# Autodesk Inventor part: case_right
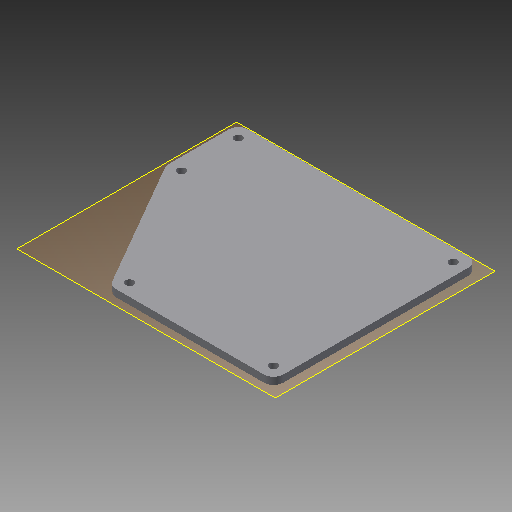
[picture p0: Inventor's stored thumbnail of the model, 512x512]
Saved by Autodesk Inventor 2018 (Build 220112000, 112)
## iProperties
Created: 2017-09
Part Number: case_right
Material: Generic
Document SubType Name: Modeling
Designer: jonas
Density: 1 g/cm^3
Appearance: Default
Mass: 23.7127 g
Surface Area: 170.193 cm^2
Volume: 23.7127 cm^3
Author: jonas
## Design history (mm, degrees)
workplane "Work Plane1"
sketch "Sketch1"
  geometry: L1 (30.736, 8.194)-(5.499, 51.895) reference; L2 (5.499, 51.895)-(10.609, 54.845) reference; L3 (6.775, 61.483)-(10.609, 54.845) reference; L4 (5.998, 61.034)-(6.775, 61.483) reference; L5 (2.998, 62.766)-(2.997, 75.995) reference; L6 (8.996, 81.996)-(90.996, 82.004) reference; L7 (96.997, 76.004)-(97.004, 9.004) reference; L8 (91.004, 3.004)-(39.736, 2.999) reference; L9 (100.004, 3.004)-(99.996, 82.004) reference; L10 (2.996, 84.995)-(96.996, 85.004) reference; L11 (-0.001, 56.224)-(-0.004, 81.995) reference; L12 (31.138, 1.498)-(0.401, 54.724) reference; L13 (97.004, 0.004)-(33.736, -0.002) reference; L14 (100.996, 82.005)-(101.004, 3.005); L15 (97.005, -0.996)-(33.737, -1.002); L16 (30.272, 0.998)-(-0.465, 54.224); L17 (-1.001, 56.224)-(-1.004, 81.995); L18 (2.996, 85.995)-(96.996, 86.004); C1 r 1.45 at (4.249, 56.56) reference; C2 r 1.45 at (4.247, 80.745) reference; C3 r 1.45 at (34.458, 4.248) reference; C4 r 1.45 at (95.754, 4.254) reference; C5 r 1.45 at (95.747, 80.754) reference; A1 r 2 centre (4.998, 62.766) between (2.998, 62.766) and (5.998, 61.034) reference; A2 r 6 centre (2.996, 81.995) between (2.997, 75.995) and (8.996, 81.996) reference; A3 r 6 centre (96.996, 82.004) between (90.996, 82.004) and (96.997, 76.004) reference; A4 r 6 centre (97.004, 3.004) between (97.004, 9.004) and (91.004, 3.004) reference; A5 r 6 centre (33.736, 2.998) between (39.736, 2.999) and (30.736, 8.194) reference; A6 r 3 centre (97.004, 3.004) between (97.004, 0.004) and (100.004, 3.004) reference; A7 r 3 centre (96.996, 82.004) between (99.996, 82.004) and (96.996, 85.004) reference; A8 r 3 centre (2.996, 81.995) between (2.996, 84.995) and (-0.004, 81.995) reference; A9 r 3 centre (2.999, 56.224) between (-0.001, 56.224) and (0.401, 54.724) reference; A10 r 3 centre (33.736, 2.998) between (31.138, 1.498) and (33.736, -0.002) reference; A11 r 4 centre (96.996, 82.004) between (100.996, 82.005) and (96.996, 86.004); A12 r 4 centre (97.004, 3.004) between (97.005, -0.996) and (101.004, 3.005); A13 r 4 centre (33.736, 2.998) between (30.272, 0.998) and (33.737, -1.002); A14 r 4 centre (2.999, 56.224) between (-1.001, 56.224) and (-0.465, 54.224); A15 r 4 centre (2.996, 81.995) between (2.996, 85.995) and (-1.004, 81.995); 1 further point
  constraints: 10 end point, 10 point on circle, 5 centre point, 9 other
  dimensions: "d0" = 1 distance between parallel lines of L18 L10; "d10" = 94 distance of L18.start L18.end (derived); "d11" = 25.77053 distance of L17.start L17.end (derived); "d12" = 61.4641 distance of L16.start L16.end (derived); "d13" = 63.26795 distance of L15.start L15.end (derived); "d14" = 79 distance of L14.start L14.end (derived); "d15" = 1.99966 vertical distance of L16.start L15.end (derived); "d16" = 3.4643 horizontal distance of L15.end L16.start (derived); "d17" = 1.99995 vertical distance of L17.start L16.end (derived); "d18" = 0.53609 horizontal distance of L17.start L16.end (derived); "d19" = 1.76777 distance of A4.centre C4.centre (derived); "d20" = 5.24988 vertical distance of C4.centre L15.start (derived); "d21" = 5.25012 horizontal distance of C4.centre L14.end (derived); "d22" = 5.25007 vertical distance of C3.centre L15.end (derived); "d23" = 4.18547 horizontal distance of C3.centre L16.start (derived); "d24" = 0.72157 horizontal distance of A10.centre C3.centre (derived); "d25" = 5.25 distance from line of C2.centre L17 (derived); "d26" = 5.25 distance from line of C2.centre L18 (derived); "d27" = 5.24997 horizontal distance of C1.centre L17.start (derived); "d28" = 0.33545 vertical distance of C1.centre L17.start (derived); "d29" = 1.24997 horizontal distance of A9.centre C1.centre (derived)
extrude "Extrusion1" new body sketch "Sketch1" distance "d1" = 3; taper "d2" = 0 deg
sketch "Sketch2"
  geometry: C1 r 1.45 at (4.249, 56.56) reference; C2 r 1.45 at (4.247, 80.745) reference; C3 r 1.45 at (95.747, 80.754) reference; C4 r 1.45 at (34.458, 4.248) reference; C5 r 1.45 at (95.754, 4.254) reference; 1 further point
hole "Hole1" sketch "Sketch2" at (4.249, 56.56), (4.247, 80.745), (34.458, 4.248), (95.754, 4.254), (95.747, 80.754) diameter "d3" = 3.5; stored, may be unused: countersink angle "d7" = 90 deg, drill point angle "d9" = 118 deg; dims "d4" = 6, "d5" = 4, "d6" = 2, "d8" = 8
body "Solid1"
node "Reference1"
